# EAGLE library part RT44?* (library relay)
Power PCB Relay SCHRACK 2 pole 8 A, DC and AC-coil Source: http://www.schrack.com/.. 5842.pdf
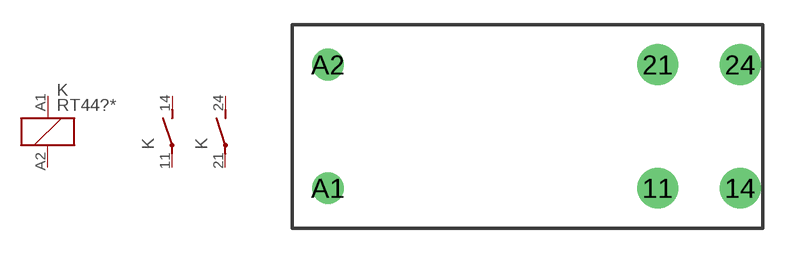
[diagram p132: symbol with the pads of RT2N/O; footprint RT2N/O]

Designator prefix K; gates 1=K 2=S 3=S

## RT444005 (MF: TYCO ELECTRONICS; MPN: 9-1393243-5; OC_FARNELL: unknown; OC_NEWARK: 16H8852), RT444006 (OC_FARNELL: unknown; OC_NEWARK: unknown), RT444012 (OC_FARNELL: unknown; OC_NEWARK: unknown), RT444024 (OC_FARNELL: unknown; OC_NEWARK: unknown), RT444048 (MPN: RT444048; OC_FARNELL: unknown; OC_NEWARK: 48M7994), RT444060 (OC_FARNELL: unknown; OC_NEWARK: unknown), RT444110 (OC_FARNELL: unknown; OC_NEWARK: unknown), RT444524 (MPN: RT444524; OC_FARNELL: unknown; OC_NEWARK: 16R6383), RT444615 (MF: TYCO ELECTRONICS; MPN: RT444615; OC_FARNELL: unknown; OC_NEWARK: 08H3757), RT444730 (OC_FARNELL: unknown; OC_NEWARK: unknown)  [RT2N/O]
11  2:P  pas
14  2:S  pas
21  3:P  pas
24  3:S  pas
A1  1:1  pas
A2  1:2  pas

## RT445005 (OC_FARNELL: unknown; OC_NEWARK: unknown), RT445006 (OC_FARNELL: unknown; OC_NEWARK: unknown), RT445012 (OC_FARNELL: unknown; OC_NEWARK: unknown), RT445024 (OC_FARNELL: unknown; OC_NEWARK: unknown), RT445048 (OC_FARNELL: unknown; OC_NEWARK: unknown), RT445060 (OC_FARNELL: unknown; OC_NEWARK: unknown), RT445110 (OC_FARNELL: unknown; OC_NEWARK: unknown), RT445524 (OC_FARNELL: unknown; OC_NEWARK: unknown), RT445615 (OC_FARNELL: unknown; OC_NEWARK: unknown), RT445730 (OC_FARNELL: unknown; OC_NEWARK: unknown)  [RT2N/O]
Pads as for RT2N/O

## Footprint RT2N/O (pad centres in mm)
Power PCB Relay DC and AC-coil SCHRACK 2 pole 8 A Source: http://www.schrack.com/.. 5842.pdf
drill 1.3 pad 2.5 round: 11 7.56,-3.78; 14 12.6,-3.78; 21 7.56,3.78; 24 12.6,3.78
drill 1.3 round: A1 -12.6,-3.78; A2 -12.6,3.78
